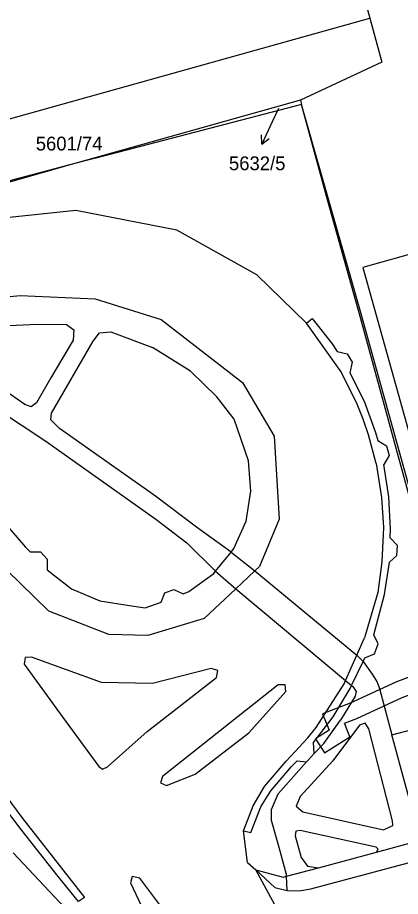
# Model space of a CAD drawing. Extents: x -821458 to -820266, y -1071458 to -1069826.
# Drawn here: x -821378.4 to -821331.3, y -1070339.6 to -1070231.3 of the extents above; entities that cross this region are included whole.
import ezdxf

# ---------------------------------------------------------------- set-up
doc = ezdxf.new("R2010")
doc.units = 0
for name, color, linetype in [('Vrstva 1', 7, 'Continuous'), ('Vrstva 13', 7, 'Continuous'), ('Vrstva 2', 7, 'Continuous'), ('Vrstva 4', 7, 'Continuous'), ('Vrstva 7', 7, 'Continuous')]:
    doc.layers.add(name, color=color, linetype=linetype)

msp = doc.modelspace()

# ---------------------------------------------------------------- linework, layer by layer
at = {"layer": 'Vrstva 1'}
for q in [(-821371.34, -1070249.29), (-821343.45, -1070241.99)]:
    msp.add_line((-821343.59, -1070241.49), q, dxfattribs=at)
for points in [[(-821328.58, -1070208.04), (-821338.41, -1070210.69), (-821341.85, -1070211.6), (-821341.24, -1070213.79), (-821339.94, -1070213.45), (-821335.06, -1070231.36)], [(-821418.73, -1070254.7), (-821405.24, -1070250.95), (-821392.2, -1070247.33), (-821335.06, -1070231.36)], [(-821335.06, -1070231.36), (-821333.58, -1070236.8), (-821343.59, -1070241.49)], [(-821343.45, -1070241.99), (-821368.76, -1070248.62), (-821371.34, -1070249.29)], [(-821328.5, -1070308.14), (-821325.62, -1070307.09), (-821327.9, -1070298.59), (-821331.9, -1070284.04), (-821336.17, -1070268.42), (-821340.27, -1070253.73), (-821343.45, -1070241.99)], [(-821329.81, -1070290.6), (-821336.19, -1070267.49), (-821343.45, -1070241.99)], [(-821371.34, -1070249.29), (-821401.67, -1070257.32), (-821402.32, -1070257.49), (-821416.89, -1070261.53)], [(-821371.34, -1070249.29), (-821401.03, -1070257.75)], [(-821318.67, -1070287.47), (-821326.54, -1070259.46), (-821335.93, -1070262.09), (-821328.07, -1070290.11)], [(-821328.8, -1070332.64), (-821332.36, -1070319.64), (-821325.16, -1070317.75)], [(-821339.31, -1070354.3), (-821341.99, -1070349.38), (-821349.09, -1070336.3), (-821345.7, -1070337.18), (-821345.3, -1070337.07), (-821341.37, -1070336.02), (-821334.24, -1070334.1), (-821328.8, -1070332.64)], [(-821309.21, -1070408.41), (-821319.78, -1070397.04), (-821333.24, -1070382.81), (-821356.7, -1070357.89), (-821358.08, -1070356.41), (-821363.03, -1070351.13), (-821378.93, -1070334.19)]]:
    msp.add_lwpolyline(points, dxfattribs=at)
at = {"layer": 'Vrstva 13'}
msp.add_lwpolyline([(-821331.87, -1070313.17), (-821337.46, -1070315.73), (-821340.87, -1070317.05), (-821340.05, -1070319.06), (-821341.73, -1070320.14), (-821340.62, -1070321.87), (-821337.51, -1070319.88), (-821338.17, -1070318.21), (-821336.66, -1070317.63), (-821331.07, -1070315.07), (-821327.15, -1070313.58), (-821327.65, -1070311.57)], close=True, dxfattribs=at)
at = {"layer": 'Vrstva 4'}
for p, q in [((-821331.71, -1070297.57), (-821331.63, -1070296.33)), ((-821354.03, -1070299.5), (-821352.12, -1070297.13)), ((-821352.12, -1070297.13), (-821349.22, -1070299.45)), ((-821354.03, -1070299.5), (-821351.55, -1070301.65)), ((-821349.22, -1070299.45), (-821351.55, -1070301.65)), ((-821349.22, -1070299.45), (-821336.65, -1070309.83)), ((-821351.55, -1070301.65), (-821338.04, -1070312.95)), ((-821336.65, -1070309.83), (-821335.69, -1070307.7)), ((-821338.04, -1070312.95), (-821336.65, -1070309.83)), ((-821337.31, -1070313.56), (-821335.88, -1070310.63)), ((-821336.65, -1070309.83), (-821335.88, -1070310.63)), ((-821335.88, -1070310.63), (-821335.66, -1070310.17)), ((-821338.04, -1070312.95), (-821337.31, -1070313.56)), ((-821340.73, -1070320.71), (-821338.68, -1070317.85)), ((-821341.9, -1070321.96), (-821340.73, -1070320.71)), ((-821377.88, -1070329.85), (-821370.15, -1070339.69)), ((-821350.1, -1070335.37), (-821350.62, -1070331.46)), ((-821350.1, -1070335.37), (-821349.09, -1070336.3)), ((-821345.3, -1070337.07), (-821345.31, -1070336.87)), ((-821345.22, -1070338.83), (-821345.3, -1070337.07))]:
    msp.add_line(p, q, dxfattribs=at)
for points in [[(-821342.86, -1070268.96), (-821348.96, -1070263), (-821358.79, -1070257.48), (-821371.24, -1070255.06), (-821381.79, -1070256.18), (-821389.72, -1070258.19), (-821399.63, -1070261.42)], [(-821387.43, -1070266.76), (-821383.68, -1070266.08), (-821378.08, -1070265.55), (-821368.86, -1070265.95), (-821360.73, -1070268.5), (-821350.71, -1070276.26)], [(-821342.86, -1070268.96), (-821342.16, -1070268.36), (-821339.7, -1070271.49), (-821339.07, -1070272.43), (-821337.84, -1070272.72), (-821337.21, -1070273.76), (-821337.51, -1070275.05), (-821335.76, -1070278.56), (-821334.36, -1070282.39), (-821334.06, -1070283.41), (-821332.98, -1070284.06), (-821332.68, -1070285.25), (-821333.34, -1070286.35)], [(-821376.09, -1070278.75), (-821376.72, -1070279.24), (-821377.52, -1070278.96), (-821387.29, -1070272.19), (-821387.78, -1070271.28), (-821387.02, -1070270.36), (-821381.2, -1070269.32), (-821376, -1070269.05), (-821372.37, -1070269.11), (-821371.47, -1070269.77), (-821371.58, -1070271.03), (-821374.3, -1070275.69), (-821376.09, -1070278.75)], [(-821334.27, -1070286.21), (-821335.21, -1070282.7), (-821335.89, -1070280.78), (-821336.59, -1070278.94), (-821338.57, -1070274.93), (-821342.86, -1070268.96)], [(-821374.23, -1070280.03), (-821369.1, -1070271.16), (-821368.33, -1070270.12), (-821366.92, -1070269.99), (-821361.82, -1070271.92)], [(-821352.12, -1070297.13), (-821351.78, -1070296.7), (-821350.29, -1070293.32), (-821349.68, -1070289.62), (-821349.98, -1070285.9), (-821351.75, -1070280.75), (-821353.89, -1070278.03), (-821357.13, -1070274.84), (-821361.82, -1070271.92)], [(-821350.71, -1070276.26), (-821346.81, -1070282.86), (-821346.22, -1070293.07), (-821348.64, -1070298.9), (-821349.22, -1070299.45)], [(-821382.6, -1070283.15), (-821383.87, -1070281.44), (-821383.79, -1070280.09), (-821382.36, -1070279.25), (-821380.79, -1070279.62), (-821374.94, -1070283.47), (-821361.39, -1070293.07), (-821357.57, -1070296.01), (-821354.03, -1070299.5)], [(-821352.12, -1070297.13), (-821356.4, -1070294.09), (-821361.43, -1070290.25), (-821373.25, -1070281.92), (-821374.31, -1070280.83), (-821374.23, -1070280.03)], [(-821351.55, -1070301.65), (-821355.43, -1070305.31), (-821362.37, -1070307.43), (-821367.16, -1070307.31), (-821374.57, -1070304.4), (-821381.51, -1070297.69), (-821389.99, -1070285.91), (-821390.73, -1070284.71)], [(-821334.27, -1070286.21), (-821333.62, -1070290.43), (-821333.35, -1070294.12), (-821333.56, -1070298.33)], [(-821332.5, -1070294.27), (-821332.72, -1070290.33), (-821333.34, -1070286.35)], [(-821382.07, -1070290.86), (-821380.02, -1070293.53), (-821377.44, -1070296.54), (-821376.84, -1070297.09), (-821375.59, -1070297.11), (-821374.76, -1070298), (-821374.77, -1070299.32), (-821371.79, -1070301.66), (-821368.28, -1070303.14), (-821364.62, -1070303.71), (-821362.7, -1070304), (-821360.72, -1070303.29), (-821360.3, -1070302.15), (-821359.16, -1070301.74), (-821358.02, -1070302.29), (-821357.33, -1070301.98), (-821354.25, -1070299.78), (-821354.03, -1070299.5)], [(-821331.63, -1070296.33), (-821332.54, -1070295.37), (-821332.5, -1070294.27)], [(-821335.66, -1070310.17), (-821334.46, -1070309.68), (-821334.02, -1070308.46), (-821334.57, -1070307.32), (-821333.23, -1070302.36), (-821332.65, -1070298.38), (-821331.71, -1070297.57)], [(-821333.56, -1070298.33), (-821334.06, -1070302.11), (-821335.69, -1070307.7)], [(-821394.96, -1070305.62), (-821389.36, -1070314.05), (-821383.69, -1070321.98), (-821377.88, -1070329.85)], [(-821376.71, -1070310.07), (-821377.49, -1070310.12), (-821377.59, -1070310.95), (-821372.9, -1070317.38), (-821368.41, -1070323.55), (-821367.97, -1070323.87), (-821367.32, -1070323.59), (-821362.44, -1070319.23), (-821353.94, -1070312.57), (-821353.77, -1070311.72), (-821354.57, -1070311.48), (-821361.82, -1070313.32), (-821368.06, -1070313.2), (-821376.71, -1070310.07)], [(-821335.88, -1070310.63), (-821334.76, -1070312.19), (-821334.16, -1070313.16), (-821333.85, -1070313.95), (-821332.36, -1070319.64)], [(-821360.58, -1070324.77), (-821360.81, -1070325.58), (-821360.09, -1070325.89), (-821356.55, -1070324.5), (-821349.93, -1070319.39), (-821345.4, -1070314.32), (-821345.49, -1070313.5), (-821346.32, -1070313.49), (-821352.24, -1070318.18), (-821360.58, -1070324.77)], [(-821345.36, -1070322.88), (-821342.7, -1070320.03), (-821341.65, -1070318.74), (-821338.22, -1070313.36), (-821338.04, -1070312.95)], [(-821339.55, -1070317.42), (-821337.49, -1070313.93), (-821337.31, -1070313.56)], [(-821337.31, -1070313.56), (-821337.15, -1070313.7), (-821336.75, -1070314.31), (-821336.86, -1070314.88), (-821338.68, -1070317.85)], [(-821343.3, -1070329.15), (-821333.35, -1070331.36), (-821332.21, -1070330.82), (-821332.25, -1070330.25), (-821335.17, -1070318.9), (-821335.61, -1070318.22), (-821336.34, -1070318.47), (-821339.59, -1070322.84), (-821343.62, -1070327.26), (-821344.1, -1070328.45), (-821343.3, -1070329.15)], [(-821341.9, -1070321.96), (-821341.99, -1070320.59), (-821339.55, -1070317.42)], [(-821342.84, -1070322.96), (-821342.66, -1070322.77), (-821341.9, -1070321.96)], [(-821350.62, -1070331.46), (-821349.41, -1070328.4), (-821348, -1070326.03), (-821345.36, -1070322.88)], [(-821350.62, -1070331.46), (-821349.71, -1070331.7), (-821348.47, -1070328.53), (-821347.22, -1070326.54), (-821344.7, -1070323.55)], [(-821345.31, -1070336.87), (-821346.21, -1070333.54), (-821347.15, -1070330.21), (-821347.16, -1070328.84), (-821346.35, -1070326.91), (-821342.84, -1070322.96)], [(-821344.7, -1070323.55), (-821343.98, -1070322.85), (-821342.84, -1070322.96)], [(-821370.15, -1070339.69), (-821370.9, -1070340.19), (-821373.42, -1070337.09), (-821375.55, -1070334.41), (-821377.96, -1070331.31), (-821380.39, -1070328.11)], [(-821345.22, -1070338.83), (-821343.74, -1070338.87), (-821342.3, -1070338.62), (-821323.1, -1070333.47), (-821308.94, -1070329.6), (-821309.41, -1070328.04)], [(-821334.24, -1070334.1), (-821334.03, -1070333.73), (-821334.28, -1070333.47), (-821343.62, -1070331.42), (-821344.16, -1070331.53), (-821344.24, -1070332.09), (-821343.49, -1070334.76), (-821342.72, -1070335.83), (-821341.37, -1070336.02)], [(-821349.09, -1070336.3), (-821346.73, -1070338.46), (-821345.22, -1070338.83)], [(-821364.49, -1070337.88), (-821362.84, -1070341.45), (-821360.23, -1070344.57), (-821356.58, -1070348.35), (-821352.86, -1070352.25), (-821352.38, -1070352.29), (-821352.37, -1070351.82), (-821358.17, -1070344.19), (-821363.34, -1070337.32), (-821364.31, -1070337.11), (-821364.49, -1070337.88)]]:
    msp.add_lwpolyline(points, dxfattribs=at)
at = {"layer": 'Vrstva 7'}
for p, q in [((-821346.29, -1070242.49), (-821347.07, -1070244.16)), ((-821347.07, -1070244.16), (-821348.34, -1070246.88)), ((-821348.34, -1070246.88), (-821348.37, -1070245.76)), ((-821348.34, -1070246.88), (-821347.46, -1070246.18))]:
    msp.add_line(p, q, dxfattribs=at)

# ---------------------------------------------------------------- texts
at = {"layer": 'Vrstva 2'}
for s, p in [('5601/74', (-821376.17, -1070247.67)), ('5632/5', (-821352.39, -1070250.1))]:
    msp.add_text(s, height=1.7, dxfattribs=at).set_placement(p)

doc.saveas('drawing.dxf')
